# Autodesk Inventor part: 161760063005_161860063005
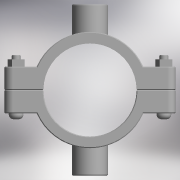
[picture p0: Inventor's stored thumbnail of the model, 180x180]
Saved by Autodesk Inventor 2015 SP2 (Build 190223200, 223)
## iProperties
Created: 2017-05
Part Number: 161760063005_161860063005
Material: Generic
Description: PLASSON DOUBLE SADDLE 63-1/2"
Document SubType Name: Modeling
Designer: KIM
Density: 1 g/cm^3
Appearance: Default
Author: KIM
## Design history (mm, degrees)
derived "16176.ipt"
feature "Solid1::16176.ipt"
feature "Solid2::16176.ipt"
tag "TaggingFeature1"
body "Solid1"
body "Solid2"
other parameters: "d0" = 78.75, "d1" = 116, "d2" = 31.5, "d3" = 63, "d4" = 84, "d5" = 0, "d6" = 5.8, "d7" = 116, "d8" = 0.1, "d10" = 0, "d11" = 0.63, "d20" = 0.63, "d23" = 0.63, "d37" = 8, "d38" = 39.5, "d39" = 0, "d40" = 3, "d41" = 5, "d42" = 0, "d43" = 6, "d44" = 3, "d45" = 0, "d46" = 0.63, "d52" = 18.631, "d53" = 18, "d54" = 0, "d55" = 16, "d57" = 0, "d58" = 68.04, "d60" = 0, "d63" = 8, "d66" = 68, "d67" = 116, "d68" = 24.2203, "d69" = 18.631, "d70" = 18, "d71" = 0, "d72" = 16, "d74" = 0, "d75" = 0.63, "d_" = 63, "B_" = 16, "G_" = 18.631, "A_" = 58, "L_" = 116, "L_1" = 84, "l_2" = 18
